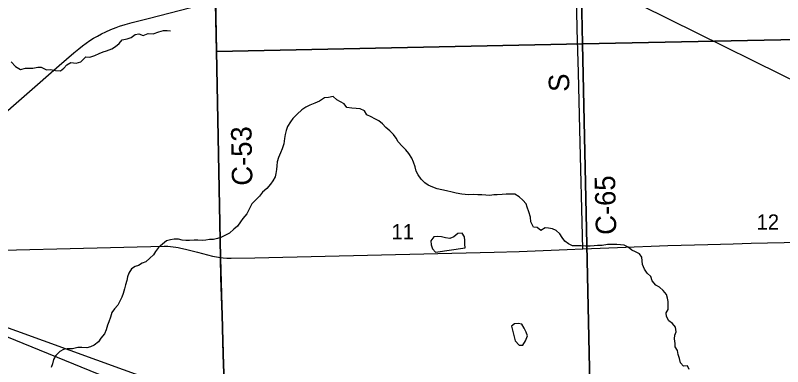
# Model space of a CAD drawing. Extents: x 0 to 34, y 0 to 22.
# Drawn here: x 6.707 to 8.833, y 17.274 to 18.248 of the extents above; entities that cross this region are included whole.
import ezdxf

# ---------------------------------------------------------------- set-up
doc = ezdxf.new("R2010")
doc.units = 0
for name, color, linetype in [('GM_X_Corporation', 7, 'Continuous'), ('GM_X_County_Road', 7, 'Continuous'), ('GM_X_County_Road_Text', 7, 'Continuous'), ('GM_X_Minor_Lake', 7, 'Continuous'), ('GM_X_Minor_River', 7, 'Continuous'), ('GM_X_Rail_Line', 7, 'Continuous'), ('GM_X_Section_Text', 7, 'Continuous'), ('GM_X_US_Route', 7, 'Continuous'), ('SH_Text', 7, 'Continuous')]:
    doc.layers.add(name, color=color, linetype=linetype)

msp = doc.modelspace()

# ---------------------------------------------------------------- linework, layer by layer
at = {"layer": 'GM_X_Corporation'}
for points in [[(9.7895, 15.1275), (9.7895, 20.2375), (9.7789, 20.2374), (8.9707, 20.221), (8.4324, 20.2139), (8.2231, 20.2112), (7.2254, 20.198), (7.2266, 20.122), (7.2291, 20.0061), (7.2317, 19.8848), (7.2344, 19.7492), (7.237, 19.6097), (7.2392, 19.4543), (7.2426, 19.2998), (7.2468, 19.0896), (7.2467, 19.0557), (7.2751, 17.5764), (7.2764, 17.5202), (7.2799, 17.4174), (7.283, 17.3071), (7.2872, 17.1772)], [(7.2872, 17.1772), (7.283, 17.3071), (7.2799, 17.4174), (7.2764, 17.5202), (7.2751, 17.5764), (7.2467, 19.0557), (7.2468, 19.0896), (7.2426, 19.2998), (7.2392, 19.4543), (7.237, 19.6097), (7.2344, 19.7492), (7.2317, 19.8848), (7.2291, 20.0061), (7.2266, 20.122), (7.2254, 20.198), (6.0786, 20.1754), (5.7004, 20.168), (4.9925, 20.1548), (3.1549, 20.1187), (2.9895, 20.1176), (2.9895, 14.989)]]:
    msp.add_lwpolyline(points, dxfattribs=at)
for points in [[(8.2571, 19.1893), (9.2644, 19.2076), (9.2853, 18.1891), (8.2786, 18.1687)], [(7.2437, 19.1696), (8.2571, 19.1893), (8.2786, 18.1687), (7.2643, 18.1469), (7.2627, 18.2368), (7.2488, 18.8774)], [(9.2853, 18.1891), (9.3117, 17.1675), (8.3006, 17.1406), (8.2786, 18.1687)], [(8.2786, 18.1687), (8.3006, 17.1406), (7.2894, 17.115), (7.2759, 17.5735), (7.2643, 18.1469)]]:
    msp.add_lwpolyline(points, close=True, dxfattribs=at)
at = {"layer": 'GM_X_County_Road'}
for points in [[(7.3099, 16.0628), (7.3051, 16.5699), (7.3048, 16.5907), (7.3, 16.7502), (7.2945, 16.9345), (7.2913, 17.051), (7.2874, 17.1766), (7.2832, 17.3066), (7.2801, 17.4169), (7.2766, 17.5196), (7.2753, 17.5759), (7.2469, 19.0552)], [(8.2793, 17.6002), (8.2707, 17.9313), (8.2675, 18.089), (8.2638, 18.2095), (8.2618, 18.3116), (8.2622, 18.3652)], [(8.2622, 18.3652), (8.3616, 18.3152), (8.5946, 18.1992), (8.8266, 18.0841), (8.9262, 18.0351), (9.125, 17.9371), (9.33, 17.8357), (9.4415, 17.781), (9.5684, 17.7185), (9.6907, 17.6578)]]:
    msp.add_lwpolyline(points, dxfattribs=at)
at = {"layer": 'GM_X_Minor_Lake'}
for points in [[(7.9527, 17.6027), (7.9523, 17.6137), (7.9526, 17.6236), (7.9509, 17.6335), (7.9444, 17.6437), (7.9326, 17.6428), (7.922, 17.634), (7.9103, 17.629), (7.8985, 17.6308), (7.8878, 17.6333), (7.8768, 17.6344), (7.8661, 17.6332), (7.8579, 17.6225), (7.8587, 17.6118), (7.863, 17.6008), (7.8707, 17.591)], [(7.9527, 17.6027), (7.9523, 17.6137), (7.9526, 17.6236), (7.9509, 17.6335), (7.9444, 17.6437), (7.9326, 17.6428), (7.922, 17.634), (7.9103, 17.629), (7.8985, 17.6308), (7.8878, 17.6333), (7.8768, 17.6344), (7.8661, 17.6332), (7.8579, 17.6225), (7.8587, 17.6118), (7.863, 17.6008), (7.8707, 17.591), (7.8703, 17.5922)], [(7.8707, 17.591), (7.9527, 17.6027)], [(8.0915, 17.3457), (8.1023, 17.3336), (8.1126, 17.3337), (8.1205, 17.3452), (8.126, 17.3589), (8.1221, 17.3691), (8.1167, 17.3805), (8.1102, 17.3915), (8.1002, 17.3937), (8.09, 17.3921), (8.0817, 17.3863)], [(8.0817, 17.3863), (8.0915, 17.3457)]]:
    msp.add_lwpolyline(points, dxfattribs=at)
at = {"layer": 'GM_X_Minor_River'}
for points in [[(7.0275, 18.1864), (7.0384, 18.1943), (7.049, 18.1964), (7.0609, 18.1921), (7.0745, 18.197), (7.0886, 18.1966), (7.104, 18.2015), (7.1169, 18.2056), (7.1272, 18.2051), (7.1367, 18.2045)], [(6.6948, 18.1186), (6.7073, 18.1056), (6.7208, 18.0971), (6.7347, 18.1013), (6.7458, 18.1015), (6.7557, 18.101), (6.7693, 18.1036), (6.7788, 18.1042), (6.7927, 18.0962), (6.8041, 18.0972), (6.8182, 18.0945), (6.8315, 18.0933), (6.8413, 18.1007), (6.8494, 18.1104), (6.861, 18.1168), (6.8752, 18.1148), (6.888, 18.1185), (6.9021, 18.1325), (6.9132, 18.1313), (6.9272, 18.1366), (6.9392, 18.1422), (6.9497, 18.1462), (6.9596, 18.1495), (6.9739, 18.1547), (6.9844, 18.1615), (6.9941, 18.1693), (7.003, 18.1801), (7.0162, 18.1827), (7.0275, 18.1864)], [(7.7887, 17.8747), (7.7787, 17.8845), (7.7672, 17.8973), (7.7622, 17.9072), (7.7541, 17.9177), (7.7441, 17.9275), (7.733, 17.937), (7.7242, 17.9472), (7.7138, 17.9547), (7.7027, 17.9607), (7.6924, 17.9663), (7.6806, 17.9719), (7.674, 17.9829), (7.6626, 17.9881), (7.6512, 17.9891), (7.639, 17.9898), (7.6253, 17.992), (7.618, 18.0018), (7.608, 18.0074), (7.5977, 18.013), (7.5873, 18.0228), (7.574, 18.0201), (7.563, 18.0185), (7.5494, 18.01), (7.5369, 18.0038), (7.5225, 17.9988), (7.5119, 17.9926), (7.5009, 17.9853), (7.4874, 17.9734), (7.4753, 17.9615), (7.4689, 17.952), (7.461, 17.9397), (7.4573, 17.9283), (7.454, 17.9169), (7.4526, 17.9062), (7.4508, 17.8918), (7.446, 17.8777), (7.4419, 17.8666), (7.4363, 17.8536), (7.4326, 17.8418), (7.4312, 17.8308), (7.4305, 17.8201), (7.4283, 17.8095), (7.4269, 17.7996), (7.4205, 17.7889), (7.4141, 17.7793), (7.4032, 17.7678), (7.3919, 17.7571), (7.3829, 17.746), (7.3723, 17.7357), (7.3621, 17.7253), (7.3558, 17.712), (7.3479, 17.6978), (7.337, 17.6844), (7.3306, 17.6749), (7.3224, 17.6634), (7.3126, 17.6546), (7.3005, 17.6442), (7.2872, 17.6369), (7.2762, 17.6315), (7.2668, 17.6292), (7.2557, 17.6264), (7.2451, 17.6259), (7.2345, 17.6243), (7.2246, 17.6239), (7.2128, 17.6242), (7.2025, 17.6248), (7.1896, 17.6236), (7.1793, 17.6235), (7.169, 17.6246), (7.1584, 17.6271), (7.147, 17.6271), (7.1367, 17.6255), (7.1257, 17.6223), (7.1148, 17.6135), (7.103, 17.6039), (7.0955, 17.5932), (7.0892, 17.5836), (7.0793, 17.5744), (7.0688, 17.5641), (7.0582, 17.5602), (7.0483, 17.5537), (7.0385, 17.5513), (7.0283, 17.5451), (7.0208, 17.5333), (7.0178, 17.523), (7.016, 17.5124), (7.0119, 17.5005), (7.0094, 17.4891), (7.0057, 17.4769), (7.0023, 17.4663), (6.9963, 17.4556), (6.9904, 17.4441), (6.9817, 17.4338), (6.9738, 17.4238), (6.9701, 17.4113), (6.966, 17.3979), (6.9623, 17.3884), (6.9586, 17.3762), (6.9534, 17.3648), (6.9436, 17.3529)], [(8.5741, 17.2655), (8.5691, 17.2758), (8.5581, 17.2749), (8.55, 17.2847), (8.5472, 17.2961), (8.5437, 17.3071), (8.5417, 17.3185), (8.5352, 17.3287), (8.5347, 17.3382), (8.5331, 17.3507), (8.5337, 17.361), (8.5375, 17.3705), (8.5362, 17.3835), (8.5274, 17.3936), (8.5178, 17.4004), (8.5105, 17.4129), (8.5104, 17.4228), (8.5152, 17.4323), (8.5159, 17.4434), (8.5154, 17.454), (8.5138, 17.4635), (8.5111, 17.4737), (8.5015, 17.485), (8.4915, 17.4937), (8.4812, 17.4997), (8.4712, 17.5118), (8.4673, 17.5232), (8.4573, 17.5326), (8.45, 17.5443), (8.4449, 17.5568), (8.4437, 17.5671), (8.4428, 17.5769), (8.4363, 17.5868), (8.4248, 17.592), (8.4145, 17.5965), (8.4049, 17.6052), (8.3939, 17.6104), (8.3836, 17.6114), (8.3737, 17.6121), (8.363, 17.6124), (8.3478, 17.6119), (8.3323, 17.6099), (8.3201, 17.6094), (8.3106, 17.6086), (8.2999, 17.6074), (8.2866, 17.6073), (8.2748, 17.6083), (8.2638, 17.6086), (8.2505, 17.6085), (8.239, 17.6141), (8.2295, 17.6216), (8.2221, 17.6318), (8.2152, 17.6417), (8.2056, 17.6511), (8.1949, 17.6559), (8.1839, 17.6578), (8.1744, 17.6581), (8.163, 17.6515), (8.1527, 17.6594), (8.1428, 17.6601), (8.1354, 17.6752), (8.1338, 17.6878), (8.1299, 17.7033), (8.1252, 17.7154), (8.1221, 17.7249), (8.1125, 17.7351), (8.1025, 17.7445), (8.0906, 17.7517), (8.0785, 17.7516), (8.0667, 17.7518), (8.0553, 17.7514), (8.0416, 17.7501), (8.0321, 17.75), (8.0211, 17.7484), (8.01, 17.7491), (7.9997, 17.7502), (7.9883, 17.7497), (7.9762, 17.7507), (7.9632, 17.7503), (7.9533, 17.7506), (7.9438, 17.752), (7.9286, 17.7542), (7.9168, 17.7571), (7.9011, 17.7612), (7.8882, 17.7637), (7.8756, 17.767), (7.8638, 17.7715), (7.8508, 17.7767), (7.8412, 17.7831), (7.8313, 17.7937), (7.8228, 17.8058), (7.8177, 17.8156), (7.8142, 17.8278), (7.8103, 17.8406), (7.8053, 17.852), (7.7972, 17.8649), (7.7887, 17.8747)], [(6.9436, 17.3529), (6.9372, 17.3426), (6.9255, 17.3337), (6.9149, 17.3291), (6.9047, 17.3263), (6.8906, 17.327), (6.8803, 17.3269), (6.8648, 17.323), (6.8503, 17.3233), (6.8404, 17.3213), (6.8302, 17.3159), (6.8189, 17.3044), (6.8122, 17.2933), (6.8096, 17.2819), (6.8059, 17.2716)]]:
    msp.add_lwpolyline(points, dxfattribs=at)
at = {"layer": 'GM_X_Rail_Line'}
msp.add_lwpolyline([(6.6479, 17.9515), (6.8284, 18.1087), (6.8692, 18.1437), (6.8823, 18.1547), (6.893, 18.1629), (6.9031, 18.1705), (6.9136, 18.1778), (6.9237, 18.1841), (6.9345, 18.1901), (6.9451, 18.1961), (6.9574, 18.2022), (6.971, 18.2085), (6.9859, 18.214), (6.9954, 18.2173), (7.0108, 18.222), (7.0305, 18.2277), (7.0748, 18.2389), (7.2218, 18.2769)], dxfattribs=at)
at = {"layer": 'GM_X_US_Route'}
for points in [[(7.2753, 17.5759), (7.283, 17.5754), (7.2928, 17.5748), (7.3048, 17.5746), (7.3702, 17.5757), (8.0334, 17.5908), (8.103, 17.5934), (8.1689, 17.5958), (8.2357, 17.5984), (8.2793, 17.6002), (8.3755, 17.6043), (8.5151, 17.6096), (8.5512, 17.6107), (8.6255, 17.6127), (8.6955, 17.6142), (8.7458, 17.6157), (8.8825, 17.6184), (9.0631, 17.6217), (9.2275, 17.6247), (9.3965, 17.6284), (9.5092, 17.6309)], [(5.486, 17.5725), (5.6721, 17.5744), (5.9049, 17.5783), (6.2235, 17.5848), (6.4485, 17.5907), (7.1191, 17.6075), (7.1293, 17.6073), (7.1366, 17.6069), (7.1443, 17.6061), (7.1511, 17.6052), (7.158, 17.6037), (7.1656, 17.6022), (7.178, 17.5993), (7.2115, 17.5908), (7.2535, 17.5802), (7.2753, 17.5759)]]:
    msp.add_lwpolyline(points, dxfattribs=at)
at = {"layer": 'SH_Text'}
msp.add_lwpolyline([(11.7478, 15.5458), (6.1293, 17.5829), (11.7478, 15.2891)], close=True, dxfattribs=at)

# ---------------------------------------------------------------- texts
at = {"layer": 'GM_X_County_Road_Text'}
for s, height, rotation, p in [('S', 0.0568, 91.2448, (8.242, 18.036)), ('C-53', 0.05682, 91.0286, (7.3639, 17.7758)), ('C-65', 0.05682, 91.3713, (8.3722, 17.6397))]:
    msp.add_text(s, height=height, rotation=rotation, dxfattribs=at).set_placement(p)
at = {"layer": 'GM_X_Section_Text'}
for s, p in [('12', (8.7606, 17.6539)), ('11', (7.7489, 17.627))]:
    msp.add_text(s, height=0.04186, rotation=0, dxfattribs=at).set_placement(p)

doc.saveas('drawing.dxf')
